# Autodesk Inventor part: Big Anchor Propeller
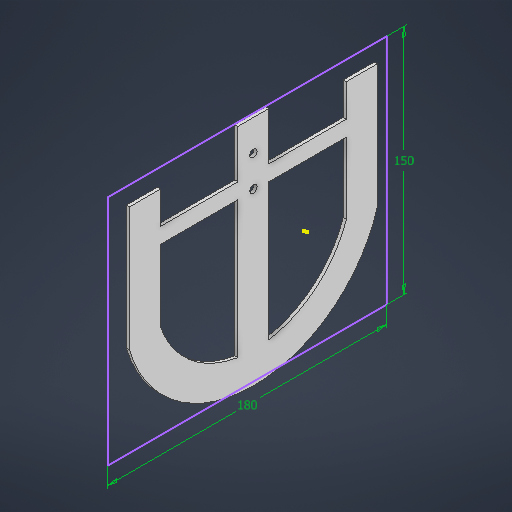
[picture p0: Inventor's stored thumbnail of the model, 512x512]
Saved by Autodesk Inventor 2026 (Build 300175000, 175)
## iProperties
Created: 2025-10
Part Number: Big Anchor Propeller
Material: Generic
Document SubType Name: Modeling
Designer: sab273
Density: 1 g/cm^3
Appearance: Default
Author: sab273
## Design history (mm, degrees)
sketch "Sketch1"
  geometry: L1 (71.477, 114.493)-(-8.523, 114.493); L2 (-8.523, -45.507)-(71.477, -45.507); L3 (-5.465, 94.493)-(0.535, 94.493); L4 (50.535, -25.507)-(50.535, 24.493); L5 (50.535, 94.493)-(50.535, 44.493); L6 (40.535, 94.493)-(40.535, 44.493); L7 (40.535, -25.507)-(40.535, 24.493); L8 (71.477, 44.493)-(76.477, 44.493); L9 (76.477, 24.493)-(71.477, 24.493); L10 (71.477, 94.493)-(71.477, 114.493); L11 (71.477, -25.507)-(71.477, -45.507); L12 (-5.465, 94.493)-(40.535, 94.493); L13 (50.535, 94.493)-(71.477, 94.493); L14 (71.477, -25.507)-(50.535, -25.507); L15 (40.535, -25.507)-(-5.465, -25.507); L16 (71.477, 44.493)-(50.535, 44.493); L17 (40.535, 44.493)-(21.477, 44.493); L18 (71.477, 24.493)-(50.535, 24.493); L19 (40.535, 24.493)-(-47.728, 24.493); L20 (71.477, 44.493)-(50.535, 44.493); L21 (40.535, 44.493)-(-47.728, 44.493); L22 (76.477, 44.493)-(81.477, 44.493); L23 (81.477, 44.493)-(81.477, 24.493); L24 (81.477, 24.493)-(76.477, 24.493); A1 r 83.333 centre (14.81, 34.493) between (-8.523, 114.493) and (-8.523, -45.507); A2 r 63.333 centre (14.81, 34.493) between (-5.465, 94.493) and (-47.728, 44.493); A3 r 63.333 centre (14.81, 34.493) between (-47.728, 24.493) and (-5.465, -25.507); 1 further point
  constraints: 48 end point, 6 point on circle, 3 centre point, 3 horizontal, 3 perpendicular, 3 point on line, 2 collinear, 2 parallel
sketch "Sketch2"
  geometry: 1 further point
extrude "Extrusion1" new body sketch "Sketch1" distance "d15" = 2; taper "d16" = 0 deg
sketch "Sketch3"
  geometry: L1 (-44.493, 81.477)-(-44.493, 50.535) reference; L2 (-24.493, 81.477)-(-44.493, 81.477) reference; C1 r 2.4 at (-34.493, 61.477); C2 r 2.4 at (-34.493, 41.477); 1 further point
  constraints: 2 centre point
extrude "Extrusion2" cut sketch "Sketch3" distance "d23" = 2; taper "d24" = 0 deg
sketch "Sketch4"
  geometry: 1 further point
sketch "Sketch5"
  geometry: L1 (-128.462, 83.838)-(51.538, 83.838); L2 (51.538, 83.838)-(51.538, -66.162); L3 (51.538, -66.162)-(-128.462, -66.162); L4 (-128.462, -66.162)-(-128.462, 83.838); 1 further point
  constraints: 8 end point, 2 parallel, 1 horizontal, 1 perpendicular
  dimensions: "d25" = 180 distance of L2.end L3.end; "d26" = 150 distance of L1.end L2.end
body "Solid1"
